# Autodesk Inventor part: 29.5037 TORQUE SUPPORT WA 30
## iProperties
Created: 2007-07
Part Number: 29.5037 TORQUE SUPPORT WA 30
Document SubType Name: Modeling
Designer: Andy Moles
Material: Steel
Density: 7.85 g/cm^3
Author: Andy Moles
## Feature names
1. Base1
